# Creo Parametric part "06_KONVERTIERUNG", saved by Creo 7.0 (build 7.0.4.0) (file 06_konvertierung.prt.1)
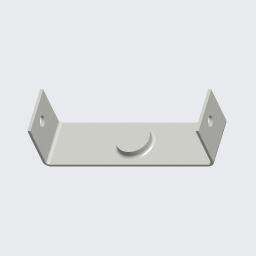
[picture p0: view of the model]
Units: millimeter Kilogram Sec (mmKs); MM, KILOGRAM, SECS
Materials in the file: S235JRG2

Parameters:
  PTC_MATERIAL_NAME = "S235JRG2"
  BENENNUNG = "XXX"
  DATUM = "XX.XX.XX"
  ERSTELLER = "ARINDA"
  TEILETYP = "Fertigungsteil"
  SMT_DFLT_BEND_REL_LENGTH_TYPE = "Through All"
  SELECT_EN_NAME = "S235JRG2"
  SELECT_DIN_NAME = "RSt37-2"
  SELECT_DIN_NUMBER = "1.0038"
  SELECT_ASTM_NAME = "A 283 M Grade 2"
  MATERIAL_GROUP = "ME_ST_Baustahl"
  STANDARD_EN_DELIVERYSPEC = "DIN EN 10025"
  STANDARD_DIN_DELIVERYSPEC = "DIN 17100"
  SCHRAUBEN_GROESSE = "M6x1"
  METRISCH = "JA"

Other parameters: MASSE, SMT_THICKNESS, SMT_PART_BEND_ALLOWANCE_FACTOR, SMT_DFLT_BEND_RADIUS, SMT_DFLT_BEND_ANGLE, SMT_DFLT_CRNR_REL_WIDTH, SMT_DFLT_CRNR_REL_DEPTH, SMT_DFLT_BEND_REL_WIDTH, SMT_DFLT_BEND_REL_DEPTH, SMT_DFLT_BEND_REL_LENGTH, SMT_DFLT_BEND_REL_ANGLE, SMT_GAP, SMT_DFLT_EDGE_TREA_WIDTH, SMT_DFLT_MITER_CUT_WIDTH, SMT_DFLT_MITER_CUT_OFFSET, BOHR_DURCHM

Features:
  1. coordinate system
  2. datum plane "T_RECHTS_Y-Z"
  3. datum plane "T_OBEN_X-Z"
  4. datum plane "T_VORNE_X-Y"
  5. datum axis
  6. datum axis
  7. datum axis
  8. protrusion
  9. protrusion
  10. hole "Bohrung 1"
  11. round "Rundung 1"
  12. round "Rundung 2"
  13. round "Rundung 3"

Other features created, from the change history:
  feature "Konvertieren(Erste Lasche)"

Other named items: T_BASIC, T_X-ACHSE, T_Y-ACHSE, T_Z-ACHSE

Layers: 00_STD-ACHSEN, 00_STD-EBENEN, 00_STD-KOORDSYS, 01_ACHSEN, SAMMELFLÄCHEN, VOLUMENGEOMETRIE

Notes: M6x1 | CLEAR |  DRILL (  | 6.600 | THRU |   -(  |  ) HOLE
